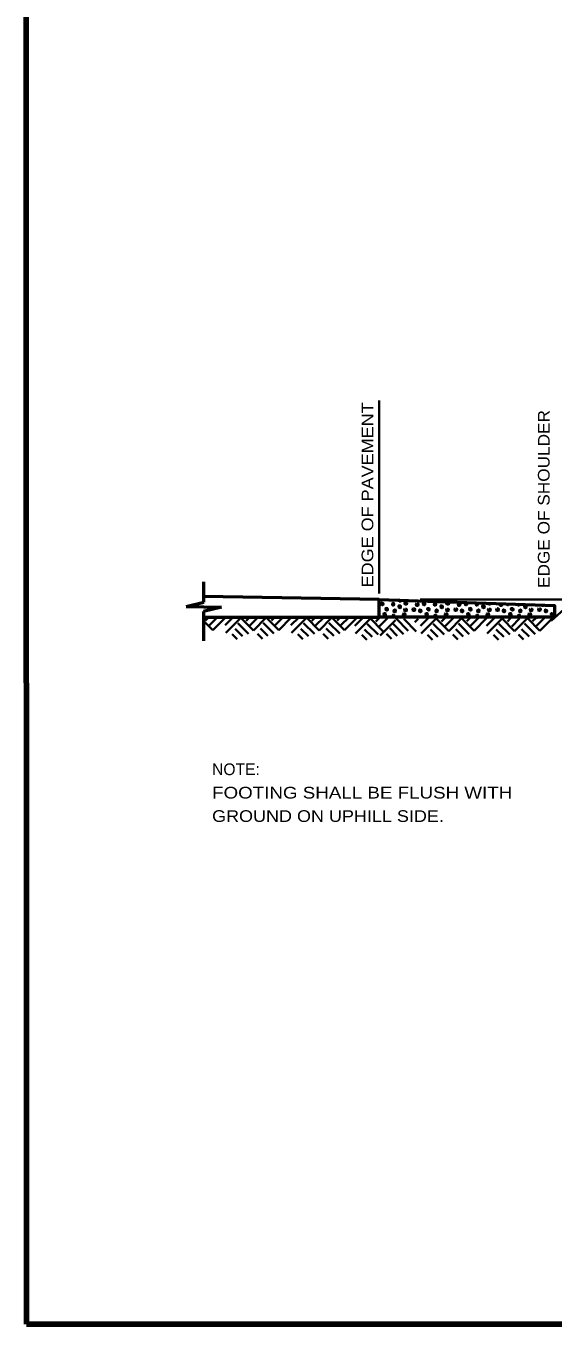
# Model space of a CAD drawing. Extents: x -27 to 828, y -12 to 532.
# Drawn here: x 30.3 to 138.5, y -0.9 to 265.3 of the extents above; entities that cross this region are included whole.
import ezdxf

# ---------------------------------------------------------------- set-up
doc = ezdxf.new("R2010")
doc.units = 0
doc.header["$LTSCALE"] = 0.96
doc.layers.add('1', color=7, linetype='Continuous', lineweight=35)

msp = doc.modelspace()

# ---------------------------------------------------------------- linework, layer by layer
at = {"layer": '1'}
for p, q in [((102.7513, 148.8739), (102.7513, 188.4681)), ((111.1513, 147.6739), (173.5513, 147.6739)), ((67.7614, 143.9695), (67.1374, 143.3455)), ((69.4894, 143.9695), (67.9054, 142.3855)), ((71.1934, 143.9695), (68.6254, 141.4015)), ((72.7294, 143.9695), (71.1454, 142.3855)), ((74.4334, 143.9695), (71.2894, 140.8255)), ((74.3134, 143.9695), (76.9534, 141.3295)), ((76.1374, 143.9695), (75.4654, 143.2735)), ((77.8654, 143.9695), (76.2094, 142.3135)), ((79.5694, 143.9695), (76.9534, 141.3295)), ((79.5694, 143.9695), (82.1374, 141.4015)), ((81.2734, 143.9695), (80.6494, 143.3455)), ((83.0014, 143.9695), (81.4174, 142.3855)), ((84.7054, 143.9695), (82.1374, 141.4015)), ((86.2414, 143.9695), (84.6574, 142.3855)), ((87.9454, 143.9695), (84.8014, 140.8255)), ((87.8254, 143.9695), (90.4654, 141.3295)), ((89.6494, 143.9695), (88.9774, 143.2735)), ((91.3774, 143.9695), (89.7214, 142.3135)), ((93.0814, 143.9695), (90.4654, 141.3295)), ((93.0814, 143.9695), (95.6494, 141.4015)), ((94.7854, 143.9695), (94.1614, 143.3455)), ((96.5134, 143.9695), (94.9294, 142.3855)), ((98.2174, 143.9695), (95.6494, 141.4015)), ((99.3247, 143.8339), (97.7407, 142.2499)), ((101.0287, 143.8339), (97.8847, 140.6899)), ((100.9087, 143.8339), (103.5487, 141.1939)), ((102.7327, 143.8339), (102.0607, 143.1379)), ((104.4607, 143.8339), (102.8047, 142.1779)), ((106.1647, 143.8339), (108.7327, 141.2659)), ((112.8367, 143.8339), (111.2527, 142.2499)), ((114.5407, 143.8339), (111.3967, 140.6899)), ((114.4207, 143.8339), (117.0607, 141.1939)), ((116.2447, 143.8339), (115.5727, 143.1379)), ((117.9727, 143.8339), (116.3167, 142.1779)), ((119.6767, 143.8339), (117.0607, 141.1939)), ((119.6767, 143.8339), (122.2447, 141.2659)), ((121.3807, 143.8339), (120.7567, 143.2099)), ((123.1087, 143.8339), (121.5247, 142.2499)), ((124.8127, 143.8339), (122.2447, 141.2659)), ((126.3487, 143.8339), (124.7647, 142.2499)), ((128.0527, 143.8339), (124.9087, 140.6899)), ((127.9327, 143.8339), (130.5727, 141.1939)), ((129.7567, 143.8339), (129.0847, 143.1379)), ((133.1887, 143.8339), (130.5727, 141.1939)), ((133.1887, 143.8339), (135.7567, 141.2659)), ((134.8927, 143.8339), (134.2687, 143.2099)), ((136.6207, 143.8339), (135.0367, 142.2499)), ((138.3247, 143.8339), (135.7567, 141.2659)), ((141.3633, 146.2314), (138.059, 143.2563)), ((66.7294, 143.2975), (68.6254, 141.4015)), ((73.1854, 141.6655), (74.7214, 140.1295)), ((73.7374, 142.8175), (75.9694, 140.6095)), ((78.3934, 141.7375), (79.9294, 140.2015)), ((78.9454, 142.8895), (81.1534, 140.6815)), ((86.6974, 141.6655), (88.2334, 140.1295)), ((87.2494, 142.8175), (89.4814, 140.6095)), ((91.9054, 141.7375), (93.4414, 140.2015)), ((92.4574, 142.8895), (94.6654, 140.6815)), ((99.7807, 141.5299), (101.3167, 139.9939)), ((100.3327, 142.6819), (102.5647, 140.4739)), ((106.1137, 143.444), (102.9697, 140.3)), ((104.944, 141.7735), (106.48, 140.2375)), ((105.5407, 142.7539), (107.7487, 140.5459)), ((107.8209, 143.6877), (110.3889, 141.1197)), ((110.7891, 143.6877), (110.1171, 142.9917)), ((113.2927, 141.5299), (114.8287, 139.9939)), ((113.8447, 142.6819), (116.0767, 140.4739)), ((118.5007, 141.6019), (120.0367, 140.0659)), ((119.0527, 142.7539), (121.2607, 140.5459)), ((126.8047, 141.5299), (128.3407, 139.9939)), ((127.3567, 142.6819), (129.5887, 140.4739)), ((131.5548, 143.7364), (129.9708, 142.1524)), ((132.0127, 141.6019), (133.5487, 140.0659)), ((132.5647, 142.7539), (134.7727, 140.5459)), ((72.5854, 140.5615), (73.6174, 139.5535)), ((77.7694, 140.6335), (78.8014, 139.6015)), ((86.0974, 140.5615), (87.1294, 139.5535)), ((91.2814, 140.6335), (92.3134, 139.6015)), ((99.1807, 140.4259), (100.2127, 139.4179)), ((104.2953, 140.6208), (105.3273, 139.6128)), ((112.6927, 140.4259), (113.7247, 139.4179)), ((117.8767, 140.4979), (118.9087, 139.4659)), ((126.2047, 140.4259), (127.2367, 139.4179)), ((131.3887, 140.4979), (132.4207, 139.4659))]:
    msp.add_line(p, q, dxfattribs=at)
at = {"layer": '1', "lineweight": 53}
for p, q in [((66.8042, 147.1014), (66.8042, 151.3014)), ((63.1673, 146.2224), (66.8042, 147.1014)), ((102.7513, 147.6739), (66.8042, 148.3014)), ((63.1673, 146.2224), (70.3662, 146.0967)), ((70.3662, 146.0967), (66.7294, 145.2175)), ((66.7294, 145.2175), (66.7294, 139.2175)), ((109.0492, 144.1131), (108.9895, 144.0175)), ((117.6412, 144.1131), (117.5815, 144.0175)), ((126.2332, 144.1131), (126.1735, 144.0175)), ((134.8252, 144.1131), (134.7655, 144.0175))]:
    msp.add_line(p, q, dxfattribs=at)
at = {"layer": '1', "lineweight": 158}
msp.add_line((821.9567, -0.9312), (30.3567, -0.9312), dxfattribs=at)
msp.add_lwpolyline([(821.9567, 525.1688), (30.2567, 525.0688), (30.3567, -0.9312)], dxfattribs=at)
at = {"layer": '1', "lineweight": 53}
msp.add_lwpolyline([(66.7294, 144.0175), (102.7513, 144.0175), (102.7513, 147.6739), (138.7294, 146.4175), (138.7294, 144.0175), (102.7513, 144.0175), (102.7513, 147.6739), (138.7294, 146.4175), (138.7294, 144.0175), (102.7513, 144.0175)], dxfattribs=at)
for points in [[(103.4572, 146.8731), (103.2412, 146.8971), (103.2412, 146.6811), (103.4572, 146.6091), (103.5532, 146.6811), (103.5292, 146.8251), (103.4812, 146.8251)], [(105.6412, 146.8731), (105.4732, 146.6811), (105.4972, 146.5851), (105.5932, 146.5851), (105.7852, 146.6331), (105.7852, 146.7531), (105.6412, 146.8251), (105.5932, 146.8251)], [(106.9204, 147.5283), (106.8652, 147.4731), (106.9852, 147.3771), (107.1052, 147.3771), (107.2972, 147.4491), (107.3136, 147.5146)], [(108.2332, 147.0891), (108.0412, 147.0171), (108.0172, 146.8731), (108.2572, 146.7771), (108.4492, 146.8251), (108.4012, 146.9451), (108.2572, 147.0411), (108.1132, 147.0411)], [(110.4892, 146.7771), (110.3692, 146.6091), (110.4412, 146.4891), (110.6092, 146.4891), (110.7532, 146.5611), (110.8012, 146.6811), (110.6092, 146.7051), (110.5132, 146.7531)], [(112.0492, 146.8731), (111.8332, 146.8971), (111.8332, 146.6811), (112.0492, 146.6091), (112.1452, 146.6811), (112.1212, 146.8251), (112.0732, 146.8251)], [(114.2332, 146.8731), (114.0652, 146.6811), (114.0892, 146.5851), (114.1852, 146.5851), (114.3772, 146.6331), (114.3772, 146.7531), (114.2332, 146.8251), (114.1852, 146.8251)], [(116.8252, 147.0891), (116.6332, 147.0171), (116.6092, 146.8731), (116.8492, 146.7771), (117.0412, 146.8251), (116.9932, 146.9451), (116.8492, 147.0411), (116.7052, 147.0411)], [(119.0812, 146.7771), (118.9612, 146.6091), (119.0332, 146.4891), (119.2012, 146.4891), (119.3452, 146.5611), (119.3932, 146.6811), (119.2012, 146.7051), (119.1052, 146.7531)], [(120.6412, 146.8731), (120.4252, 146.8971), (120.4252, 146.6811), (120.6412, 146.6091), (120.7372, 146.6811), (120.7132, 146.8251), (120.6652, 146.8251)], [(122.8252, 146.8731), (122.6572, 146.6811), (122.6812, 146.5851), (122.7772, 146.5851), (122.9692, 146.6331), (122.9692, 146.7531), (122.8252, 146.8251), (122.7772, 146.8251)], [(125.204, 146.8898), (125.2012, 146.8731), (125.4412, 146.7771), (125.6332, 146.8251), (125.613, 146.8755)], [(127.6732, 146.7771), (127.5532, 146.6091), (127.6252, 146.4891), (127.7932, 146.4891), (127.9372, 146.5611), (127.9852, 146.6811), (127.7932, 146.7051), (127.6972, 146.7531)], [(129.0172, 146.7567), (129.0172, 146.6811), (129.2332, 146.6091), (129.3292, 146.6811), (129.3184, 146.7461)], [(131.2498, 146.6787), (131.2732, 146.5851), (131.3692, 146.5851), (131.5612, 146.6331), (131.5612, 146.6678)], [(136.2073, 146.5056), (136.2172, 146.4891), (136.3852, 146.4891), (136.4044, 146.4987)], [(102.7513, 145.2157), (102.7852, 145.2411), (102.7513, 145.3428)], [(104.0092, 144.7131), (103.7212, 144.7131), (103.7452, 144.5931), (103.8892, 144.5211), (104.0092, 144.4971), (104.0572, 144.5211), (104.0332, 144.6651), (103.9612, 144.7851)], [(104.3932, 145.7451), (104.1052, 145.7451), (104.1292, 145.6491), (104.2732, 145.5771), (104.3932, 145.5531), (104.4652, 145.5771), (104.4172, 145.7211), (104.3452, 145.8171)], [(105.7132, 144.4251), (105.5452, 144.2571), (105.5692, 144.1371), (105.6892, 144.1371), (105.8572, 144.1851), (105.8572, 144.3291), (105.7132, 144.4011), (105.6892, 144.4011)], [(105.9532, 145.5051), (105.7852, 145.3371), (105.8092, 145.2171), (105.9052, 145.2171), (106.0972, 145.2651), (106.0972, 145.4091), (105.9532, 145.4811), (105.9052, 145.4811)], [(106.9372, 146.3451), (106.8172, 146.2971), (106.8172, 146.1771), (106.9852, 146.0331), (107.1532, 146.0811), (107.1532, 146.2251), (107.0812, 146.2971), (106.9132, 146.3211), (106.8412, 146.3211)], [(107.8012, 144.7371), (107.7052, 144.5451), (107.7772, 144.4491), (107.9452, 144.4491), (108.0892, 144.5211), (108.1132, 144.6171), (107.9452, 144.6651), (107.8492, 144.6891)], [(108.0652, 145.6971), (107.9692, 145.5291), (108.0412, 145.4091), (108.2092, 145.4091), (108.3532, 145.4811), (108.4012, 145.6011), (108.2092, 145.6251), (108.1132, 145.6731)], [(109.4533, 144.0175), (109.4572, 144.0411), (109.2412, 144.0411), (109.0732, 144.0651), (109.0012, 144.0651)], [(109.7692, 145.7691), (109.6732, 145.6011), (109.7452, 145.4811), (109.9132, 145.4811), (110.0572, 145.5531), (110.1052, 145.6731), (109.9132, 145.6971), (109.8172, 145.7451)], [(111.2812, 145.4331), (111.0652, 145.4571), (111.0652, 145.2411), (111.2812, 145.1691), (111.3772, 145.2411), (111.3292, 145.3851), (111.3052, 145.3851)], [(112.6012, 144.7131), (112.3132, 144.7131), (112.3372, 144.5931), (112.4812, 144.5211), (112.6012, 144.4971), (112.6492, 144.5211), (112.6252, 144.6651), (112.5532, 144.7851)], [(112.9852, 145.7451), (112.6972, 145.7451), (112.7212, 145.6491), (112.8652, 145.5771), (112.9852, 145.5531), (113.0572, 145.5771), (113.0092, 145.7211), (112.9372, 145.8171)], [(114.3052, 144.4251), (114.1372, 144.2571), (114.1612, 144.1371), (114.2812, 144.1371), (114.4492, 144.1851), (114.4492, 144.3291), (114.3052, 144.4011), (114.2812, 144.4011)], [(114.5452, 145.5051), (114.3772, 145.3371), (114.4012, 145.2171), (114.4972, 145.2171), (114.6892, 145.2651), (114.6892, 145.4091), (114.5452, 145.4811), (114.4972, 145.4811)], [(115.5292, 146.3451), (115.4092, 146.2971), (115.4092, 146.1771), (115.5772, 146.0331), (115.7452, 146.0811), (115.7452, 146.2251), (115.6732, 146.2971), (115.5052, 146.3211), (115.4332, 146.3211)], [(116.3932, 144.7371), (116.2972, 144.5451), (116.3692, 144.4491), (116.5372, 144.4491), (116.6812, 144.5211), (116.7052, 144.6171), (116.5372, 144.6651), (116.4412, 144.6891)], [(116.6572, 145.6971), (116.5612, 145.5291), (116.6332, 145.4091), (116.8012, 145.4091), (116.9452, 145.4811), (116.9932, 145.6011), (116.8012, 145.6251), (116.7052, 145.6731)], [(118.0453, 144.0175), (118.0492, 144.0411), (117.8332, 144.0411), (117.6652, 144.0651), (117.5932, 144.0651)], [(118.3612, 145.7691), (118.2652, 145.6011), (118.3372, 145.4811), (118.5052, 145.4811), (118.6492, 145.5531), (118.6972, 145.6731), (118.5052, 145.6971), (118.4092, 145.7451)], [(119.8732, 145.4331), (119.6572, 145.4571), (119.6572, 145.2411), (119.8732, 145.1691), (119.9692, 145.2411), (119.9212, 145.3851), (119.8972, 145.3851)], [(121.1932, 144.7131), (120.9052, 144.7131), (120.9292, 144.5931), (121.0732, 144.5211), (121.1932, 144.4971), (121.2412, 144.5211), (121.2172, 144.6651), (121.1452, 144.7851)], [(121.5772, 145.7451), (121.2892, 145.7451), (121.3132, 145.6491), (121.4572, 145.5771), (121.5772, 145.5531), (121.6492, 145.5771), (121.6012, 145.7211), (121.5292, 145.8171)], [(122.8972, 144.4251), (122.7292, 144.2571), (122.7532, 144.1371), (122.8732, 144.1371), (123.0412, 144.1851), (123.0412, 144.3291), (122.8972, 144.4011), (122.8732, 144.4011)], [(123.1372, 145.5051), (122.9692, 145.3371), (122.9932, 145.2171), (123.0892, 145.2171), (123.2812, 145.2651), (123.2812, 145.4091), (123.1372, 145.4811), (123.0892, 145.4811)], [(124.1212, 146.3451), (124.0012, 146.2971), (124.0012, 146.1771), (124.1692, 146.0331), (124.3372, 146.0811), (124.3372, 146.2251), (124.2652, 146.2971), (124.0972, 146.3211), (124.0252, 146.3211)], [(124.9852, 144.7371), (124.8892, 144.5451), (124.9612, 144.4491), (125.1292, 144.4491), (125.2732, 144.5211), (125.2972, 144.6171), (125.1292, 144.6651), (125.0332, 144.6891)], [(125.2492, 145.6971), (125.1532, 145.5291), (125.2252, 145.4091), (125.3932, 145.4091), (125.5372, 145.4811), (125.5852, 145.6011), (125.3932, 145.6251), (125.2972, 145.6731)], [(126.6373, 144.0175), (126.6412, 144.0411), (126.4252, 144.0411), (126.2572, 144.0651), (126.1852, 144.0651)], [(126.9532, 145.7691), (126.8572, 145.6011), (126.9292, 145.4811), (127.0972, 145.4811), (127.2412, 145.5531), (127.2892, 145.6731), (127.0972, 145.6971), (127.0012, 145.7451)], [(128.4652, 145.4331), (128.2492, 145.4571), (128.2492, 145.2411), (128.4652, 145.1691), (128.5612, 145.2411), (128.5132, 145.3851), (128.4892, 145.3851)], [(129.7852, 144.7131), (129.4972, 144.7131), (129.5212, 144.5931), (129.6652, 144.5211), (129.7852, 144.4971), (129.8332, 144.5211), (129.8092, 144.6651), (129.7372, 144.7851)], [(130.1692, 145.7451), (129.8812, 145.7451), (129.9052, 145.6491), (130.0492, 145.5771), (130.1692, 145.5531), (130.2412, 145.5771), (130.1932, 145.7211), (130.1212, 145.8171)], [(131.4892, 144.4251), (131.3212, 144.2571), (131.3452, 144.1371), (131.4652, 144.1371), (131.6332, 144.1851), (131.6332, 144.3291), (131.4892, 144.4011), (131.4652, 144.4011)], [(131.7292, 145.5051), (131.5612, 145.3371), (131.5852, 145.2171), (131.6812, 145.2171), (131.8732, 145.2651), (131.8732, 145.4091), (131.7292, 145.4811), (131.6812, 145.4811)], [(132.7132, 146.3451), (132.5932, 146.2971), (132.5932, 146.1771), (132.7612, 146.0331), (132.9292, 146.0811), (132.9292, 146.2251), (132.8572, 146.2971), (132.6892, 146.3211), (132.6172, 146.3211)], [(133.5772, 144.7371), (133.4812, 144.5451), (133.5532, 144.4491), (133.7212, 144.4491), (133.8652, 144.5211), (133.8892, 144.6171), (133.7212, 144.6651), (133.6252, 144.6891)], [(133.8412, 145.6971), (133.7452, 145.5291), (133.8172, 145.4091), (133.9852, 145.4091), (134.1292, 145.4811), (134.1772, 145.6011), (133.9852, 145.6251), (133.8892, 145.6731)], [(135.2293, 144.0175), (135.2332, 144.0411), (135.0172, 144.0411), (134.8492, 144.0651), (134.7772, 144.0651)], [(135.5452, 145.7691), (135.4492, 145.6011), (135.5212, 145.4811), (135.6892, 145.4811), (135.8332, 145.5531), (135.8812, 145.6731), (135.6892, 145.6971), (135.5932, 145.7451)], [(137.0572, 145.4331), (136.8412, 145.4571), (136.8412, 145.2411), (137.0572, 145.1691), (137.1532, 145.2411), (137.1052, 145.3851), (137.0812, 145.3851)], [(138.3772, 144.7131), (138.0892, 144.7131), (138.1132, 144.5931), (138.2572, 144.5211), (138.3772, 144.4971), (138.4252, 144.5211), (138.4012, 144.6651), (138.3292, 144.7851)]]:
    msp.add_spline(points, degree=3, dxfattribs=at)

# ---------------------------------------------------------------- texts
at = {"layer": '1'}
for s, width, p in [('EDGE OF PAVEMENT', 1.15, (101.5613, 150.1569)), ('EDGE OF SHOULDER', 1.1, (137.7505, 150.0334))]:
    msp.add_text(s, height=2.4, rotation=90, dxfattribs=dict(at, width=width)).set_placement(p)
msp.add_text('NOTE:', height=2.4, dxfattribs=at).set_placement((68.4679, 111.6438))
for s, width, p in [('FOOTING SHALL BE FLUSH WITH', 1.2, (68.4679, 106.8438)), ('GROUND ON UPHILL SIDE.', 1.15, (68.4679, 102.0438))]:
    msp.add_text(s, height=2.4, dxfattribs=dict(at, width=width)).set_placement(p)

doc.saveas('drawing.dxf')
